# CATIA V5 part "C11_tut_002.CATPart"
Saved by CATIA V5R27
Part number: Part2
Bounding box of the stored display mesh (mm): x 0 to 175, y -36.659 to 105, z 0 to 36.653
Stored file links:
  E:\_Deepak\2017_Deepak\CATIA\Resources\Tutorial Files\Tutorials\c11_catia_v5_6r2016_tut\C11_tut_002.CATPart
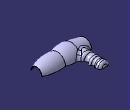
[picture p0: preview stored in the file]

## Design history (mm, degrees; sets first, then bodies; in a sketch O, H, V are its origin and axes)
Body1 (main body)
  Plane1: type Offset, RefPlane yz-plane, Offset 50
  Set1
    Plane2: type Offset, RefPlane yz-plane, Offset 100 {= Plane1.Offset+`Plane2.Relative Offset`}
    Plane3: type Offset, RefPlane yz-plane, Offset 175
  Sketch1 on yz-plane, origin (0, 0, 0), H (0, 1, 0), V (0, 0, 1)
    arc A1 centre (0, 0) radius 25 from (25, 0) to (-25, 0) ccw
    point P1 (-25, 0)
    radius A1 = 25
  Sketch2 on Plane1, origin (50, 0, 0), H (0, 1, 0), V (0, 0, 1)
    arc A1 centre (0, 0) radius 35 from (35, 0) to (-35, 0) ccw
    point P1 (-35, 0)
    radius A1 = 35
  Sketch3 on Plane2, origin (100, 0, 0), H (0, 1, 0), V (0, 0, 1)
    arc A1 centre (0, 0) radius 30 from (30, 0) to (-30, 0) ccw
    point P1 (-30, 0)
    radius A1 = 30
  Sketch4 on Plane3, origin (175, 0, 0), H (0, 1, 0), V (0, 0, 1)
    arc A1 centre (0, 0) radius 20 from (20, 0) to (-20, 0) ccw
    point P1 (-20, 0)
    radius A1 = 20
  Sketch5 on xy-plane, origin (0, 0, 0), H (1, 0, 0), V (0, 1, 0)
    point P1 (0, -25)
    line L1 (0, -25) -> (50, -35)
    point P2 (50, -35)
    reference projected point E1 (50, -35) from Sketch2.P1
    reference projected point E2 (0, -25) from Sketch1.P1
    arc A1 centre (66.816, 49.3399) radius 86 from (50, -35) to (100, -30) ccw
    point P4 (100, -30)
    reference projected point E3 (100, -30) from Sketch3.P1
    arc A2 centre (121.7543, 93.0924) radius 125 from (100, -30) to (175, -20) ccw
    point P6 (175, -20)
    reference projected point E4 (175, -20) from Sketch4.P1
    radius A1 = 86
    radius A2 = 125
    coincidence: P1 V, P2 E1, P1 E2, P4 E3, E4 P6
  Sketch6 on xy-plane, origin (0, 0, 0), H (1, 0, 0), V (0, 1, 0)
    arc A1 centre (121.7543, -93.0924) radius 125 from (100, 30) to (175, 20) cw
    arc A2 centre (66.816, -49.3399) radius 86 from (50, 35) to (100, 30) cw
    line L1 (0, 25) -> (50, 35)
    fix: A1, L1, A2
  Loft1: Sections (Sketch1; Sketch2; Sketch3; Sketch4), Guides (Sketch5; Sketch6)
  Sketch7 on xy-plane, origin (0, 0, 0), H (1, 0, 0), V (0, 1, 0)
    point P1 (15, 105)
    line L1 (15, 105) -> (15, 0)
    point P2 (15, 0)
    point P3 (15, 105)
    distance H P1 = 105
    distance V L1 = 15
    coincidence: P2 H, P3 P1
    vertical: L1 V
  Plane4: type Normal, Curve Sketch7, RefPoint Sketch7.P3, Ratio 0
  Sketch8 on Plane4, origin (0, 105, 0), H (1, 0, 0), V (0, 0, 1)
    arc A1 centre (32.5, 0) radius 17.5 from (15, 0) to (50, 0) cw
    point P1 (32.5, 0)
    point P2 (15, 0)
    point P3 (50, 0)
    reference projected line E1 (0, 0) -> (-50, 0) from edge of Loft1
    reference projected point E2 (15, 0) from Sketch7.P2
    radius A1 = 17.5
    coincidence: P2 H, P3 H, P1 E1, E2 P2
  Sketch9 on xy-plane, origin (0, 0, 0), H (1, 0, 0), V (0, 1, 0)
    line L1 (50, 105) -> (51.989, 90.8478)
    point P1 (50, 105)
    arc A1 centre (45.0571, 89.8736) radius 7 from (51.989, 90.8478) to (49.6106, 84.5571) cw
    arc A2 centre (53.5135, 80) radius 6 from (49.6106, 84.5571) to (51.6373, 74.3009) ccw
    point P5 (53.5135, 80)
    point P6 (51.6373, 74.3009)
    arc A3 centre (50.1519, 69.7891) radius 4.75 from (51.6373, 74.3009) to (52.3972, 65.6033) cw
    point P8 (51.6373, 74.3009)
    arc A4 centre (56.6515, 57.6723) radius 9 from (52.3972, 65.6033) to (52.5866, 49.6425) ccw
    point P10 (56.6515, 57.6723)
    arc A5 centre (47.1667, 38.9362) radius 12 from (52.5866, 49.6425) to (59.0499, 40.6063) cw
    axis line L2 (50, 105) -> (61.1145, 25.9165)
    line L3 (59.0499, 40.6063) -> (62.3136, 17.3845)
    reference projected point E1 (50, 105) from Sketch8.P3
    reference projected line E2 (50, 105) -> (15, 105) from Sketch8.A1
    radius A1 = 7
    radius A2 = 6
    radius A3 = 4.75
    radius A4 = 9
    radius A5 = 12
    distance P5 P1 V = 25
    angle L1 E2 = 98
    tangency: A2 A1, A3 L2, A3 A2, A3 A4, A5 A4, A5 L2, L3 A5, L3 L2, A1 L1
    coincidence: P8 A2, L2 L1, P5 L2, P8 P6, P10 L2, P1 E1
  Loft2: Sections Sketch8, Guides (Sketch9; Sketch7)
  Trim1: Trimmed (Loft1; Loft2)
  Line1: type PtPt, FirstPoint vertex [face of Loft1], SecondPoint vertex [face of Loft1]
  Line2: type PtPt, FirstPoint vertex [face of Loft2], SecondPoint vertex [face of Loft2]
  Line3: type PtPt, FirstPoint vertex [face of Loft1], SecondPoint vertex [face of Loft1]
  Fill1: Boundary (Line3; edge of Loft1)
  Fill2: Boundary (edge of Loft1; Line1)
  Fill3: Boundary (edge of Loft2; Line2)
  Join1: Elements (Fill2; Fill3; Fill1; Trim1)
  CloseSurface1: CloseElement Join1
  Fillet1: radius 12, on edge [face of CloseSurface1 | face of CloseSurface1]
  Fillet2: radius 8, on edge [face of CloseSurface1 | face of CloseSurface1]
  Shell1: ExtOffset 0, Face (face of CloseSurface1; face of CloseSurface1; face of CloseSurface1), IntOffset 1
